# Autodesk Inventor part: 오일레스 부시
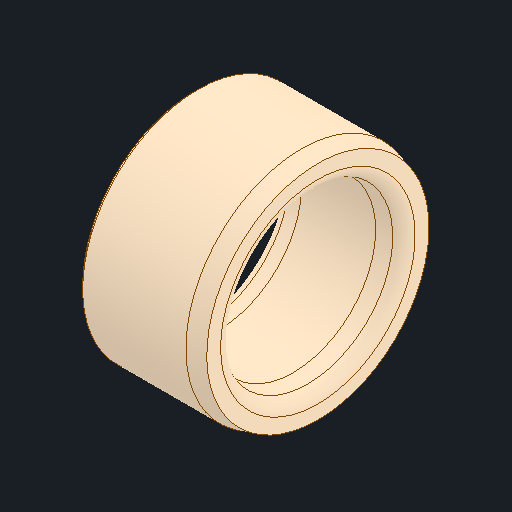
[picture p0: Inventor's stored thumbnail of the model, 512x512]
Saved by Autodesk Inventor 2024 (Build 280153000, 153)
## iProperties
Created: 2024-05
Part Number: 오일레스 부시
Material: 구리, 합금
Document SubType Name: Modeling
Designer: kh_501
Density: 8.92 g/cm^3
Appearance: 기본값
Sending System: Autodesk Inventor 2025
Preprocessor: ST-DEVELOPER v20
Author: jhkim
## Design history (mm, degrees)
feature "솔리드1"
node "솔리드2"
